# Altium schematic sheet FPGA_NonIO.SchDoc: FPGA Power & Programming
size A4; DocumentNumber: 8; SheetNumber: 8; SheetTotal: 23; Organization: Altium Limited.; Address1: Level 3, 12a Rodborough Rd; Address2: Frenchs Forest 2086; Address3: NSW; Address4: AUSTRALIA
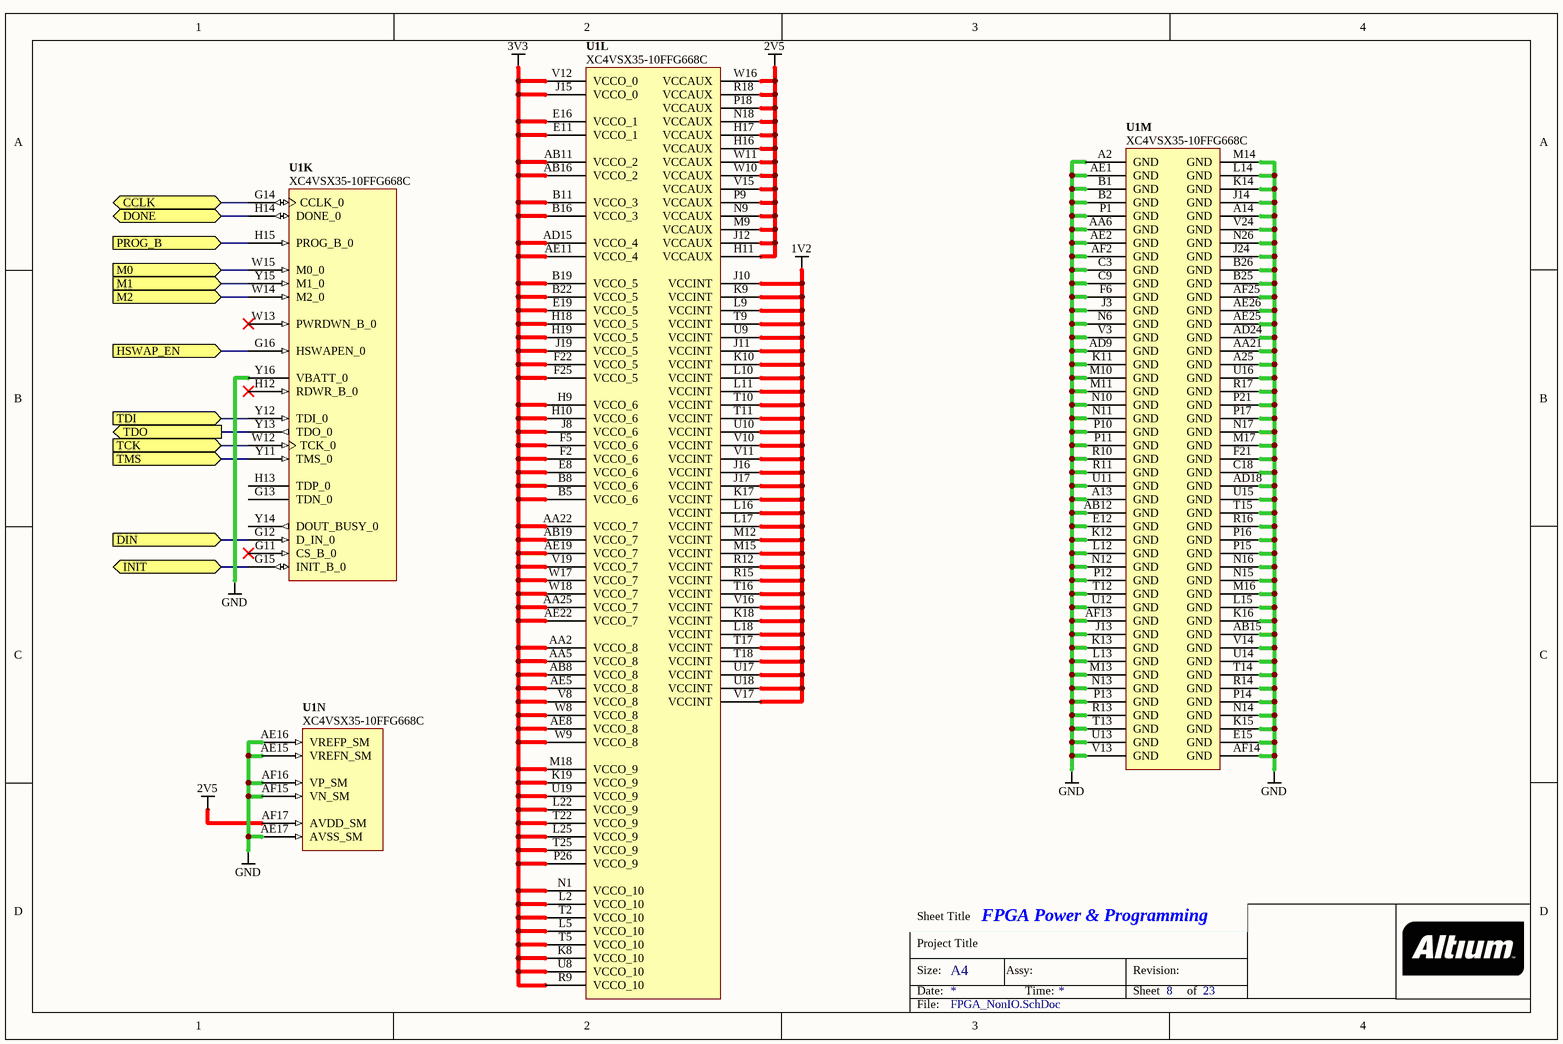
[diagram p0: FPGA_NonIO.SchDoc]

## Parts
U1  XC4VSX35-10FFG668C  [XC4VLX25-10FF668C]  (parts K,L,M,N of 14)

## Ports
CCLK (bidir), DIN (in), DONE (bidir), HSWAP_EN (in), INIT (bidir), M0 (in), M1 (in), M2 (in), PROG_B (in), TCK (in), TDI (in), TDO (out), TMS (in)

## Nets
1V2: U1.J10(VCCINT) U1.J11(VCCINT) U1.J16(VCCINT) U1.J17(VCCINT) U1.K9(VCCINT) U1.K10(VCCINT) U1.K17(VCCINT) U1.K18(VCCINT) U1.L9(VCCINT) U1.L10(VCCINT) U1.L11(VCCINT) U1.L16(VCCINT) U1.L17(VCCINT) U1.L18(VCCINT) U1.M12(VCCINT) U1.M15(VCCINT) U1.R12(VCCINT) U1.R15(VCCINT) U1.T9(VCCINT) U1.T10(VCCINT) U1.T11(VCCINT) U1.T16(VCCINT) U1.T17(VCCINT) U1.T18(VCCINT) U1.U9(VCCINT) U1.U10(VCCINT) U1.U17(VCCINT) U1.U18(VCCINT) U1.V10(VCCINT) U1.V11(VCCINT) U1.V16(VCCINT) U1.V17(VCCINT)
2V5: U1.AF17(AVDD_SM) U1.H11(VCCAUX) U1.H16(VCCAUX) U1.H17(VCCAUX) U1.J12(VCCAUX) U1.M9(VCCAUX) U1.N9(VCCAUX) U1.N18(VCCAUX) U1.P9(VCCAUX) U1.P18(VCCAUX) U1.R18(VCCAUX) U1.V15(VCCAUX) U1.W10(VCCAUX) U1.W11(VCCAUX) U1.W16(VCCAUX)
3V3: U1.AA2(VCCO_8) U1.AA5(VCCO_8) U1.AA22(VCCO_7) U1.AA25(VCCO_7) U1.AB8(VCCO_8) U1.AB11(VCCO_2) U1.AB16(VCCO_2) U1.AB19(VCCO_7) U1.AD15(VCCO_4) U1.AE5(VCCO_8) U1.AE8(VCCO_8) U1.AE11(VCCO_4) U1.AE19(VCCO_7) U1.AE22(VCCO_7) U1.B5(VCCO_6) U1.B8(VCCO_6) U1.B11(VCCO_3) U1.B16(VCCO_3) U1.B19(VCCO_5) U1.B22(VCCO_5) U1.E8(VCCO_6) U1.E11(VCCO_1) U1.E16(VCCO_1) U1.E19(VCCO_5) U1.F2(VCCO_6) U1.F5(VCCO_6) U1.F22(VCCO_5) U1.F25(VCCO_5) U1.H9(VCCO_6) U1.H10(VCCO_6) U1.H18(VCCO_5) U1.H19(VCCO_5) U1.J8(VCCO_6) U1.J15(VCCO_0) U1.J19(VCCO_5) U1.K8(VCCO_10) U1.K19(VCCO_9) U1.L2(VCCO_10) U1.L5(VCCO_10) U1.L22(VCCO_9) U1.L25(VCCO_9) U1.M18(VCCO_9) U1.N1(VCCO_10) U1.P26(VCCO_9) U1.R9(VCCO_10) U1.T2(VCCO_10) U1.T5(VCCO_10) U1.T22(VCCO_9) U1.T25(VCCO_9) U1.U8(VCCO_10) U1.U19(VCCO_9) U1.V8(VCCO_8) U1.V12(VCCO_0) U1.V19(VCCO_7) U1.W8(VCCO_8) U1.W9(VCCO_8) U1.W17(VCCO_7) U1.W18(VCCO_7)
GND: U1.A2(GND) U1.A13(GND) U1.A14(GND) U1.A25(GND) U1.AA6(GND) U1.AA21(GND) U1.AB12(GND) U1.AB15(GND) U1.AD9(GND) U1.AD18(GND) U1.AD24(GND) U1.AE1(GND) U1.AE2(GND) U1.AE15(VREFN_SM) U1.AE16(VREFP_SM) U1.AE17(AVSS_SM) U1.AE25(GND) U1.AE26(GND) U1.AF2(GND) U1.AF13(GND) U1.AF14(GND) U1.AF15(VN_SM) U1.AF16(VP_SM) U1.AF25(GND) U1.B1(GND) U1.B2(GND) U1.B25(GND) U1.B26(GND) U1.C3(GND) U1.C9(GND) U1.C18(GND) U1.E12(GND) U1.E15(GND) U1.F6(GND) U1.F21(GND) U1.J3(GND) U1.J13(GND) U1.J14(GND) U1.J24(GND) U1.K11(GND) U1.K12(GND) U1.K13(GND) U1.K14(GND) U1.K15(GND) U1.K16(GND) U1.L12(GND) U1.L13(GND) U1.L14(GND) U1.L15(GND) U1.M10(GND) U1.M11(GND) U1.M13(GND) U1.M14(GND) U1.M16(GND) U1.M17(GND) U1.N6(GND) U1.N10(GND) U1.N11(GND) U1.N12(GND) U1.N13(GND) U1.N14(GND) U1.N15(GND) U1.N16(GND) U1.N17(GND) U1.N26(GND) U1.P1(GND) U1.P10(GND) U1.P11(GND) U1.P12(GND) U1.P13(GND) U1.P14(GND) U1.P15(GND) U1.P16(GND) U1.P17(GND) U1.P21(GND) U1.R10(GND) U1.R11(GND) U1.R13(GND) U1.R14(GND) U1.R16(GND) U1.R17(GND) U1.T12(GND) U1.T13(GND) U1.T14(GND) U1.T15(GND) U1.U11(GND) U1.U12(GND) U1.U13(GND) U1.U14(GND) U1.U15(GND) U1.U16(GND) U1.V3(GND) U1.V13(GND) U1.V14(GND) U1.V24(GND) U1.Y16(VBATT_0)
CCLK: U1.G14(CCLK_0) ; port CCLK
DIN: U1.G12(D_IN_0) ; port DIN
DONE: U1.H14(DONE_0) ; port DONE
HSWAP_EN: U1.G16(HSWAPEN_0) ; port HSWAP_EN
INIT: U1.G15(INIT_B_0) ; port INIT
M0: U1.W15(M0_0) ; port M0
M1: U1.Y15(M1_0) ; port M1
M2: U1.W14(M2_0) ; port M2
PROG_B: U1.H15(PROG_B_0) ; port PROG_B
TCK: U1.W12(TCK_0) ; port TCK
TDI: U1.Y12(TDI_0) ; port TDI
TDO: U1.Y13(TDO_0) ; port TDO
TMS: U1.Y11(TMS_0) ; port TMS

Not connected (* = marked no-connect by the designer): U1 G11(CS_B_0)* G13(TDN_0) H12(RDWR_B_0)* H13(TDP_0) W13(PWRDWN_B_0)* Y14(DOUT_BUSY_0)

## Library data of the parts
U1 = D-241-0021: FPGA, Xilinx Virtex-4, XC4VSX35; Supply Voltage: mV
